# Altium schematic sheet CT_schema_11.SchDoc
size 385 x 278 mm
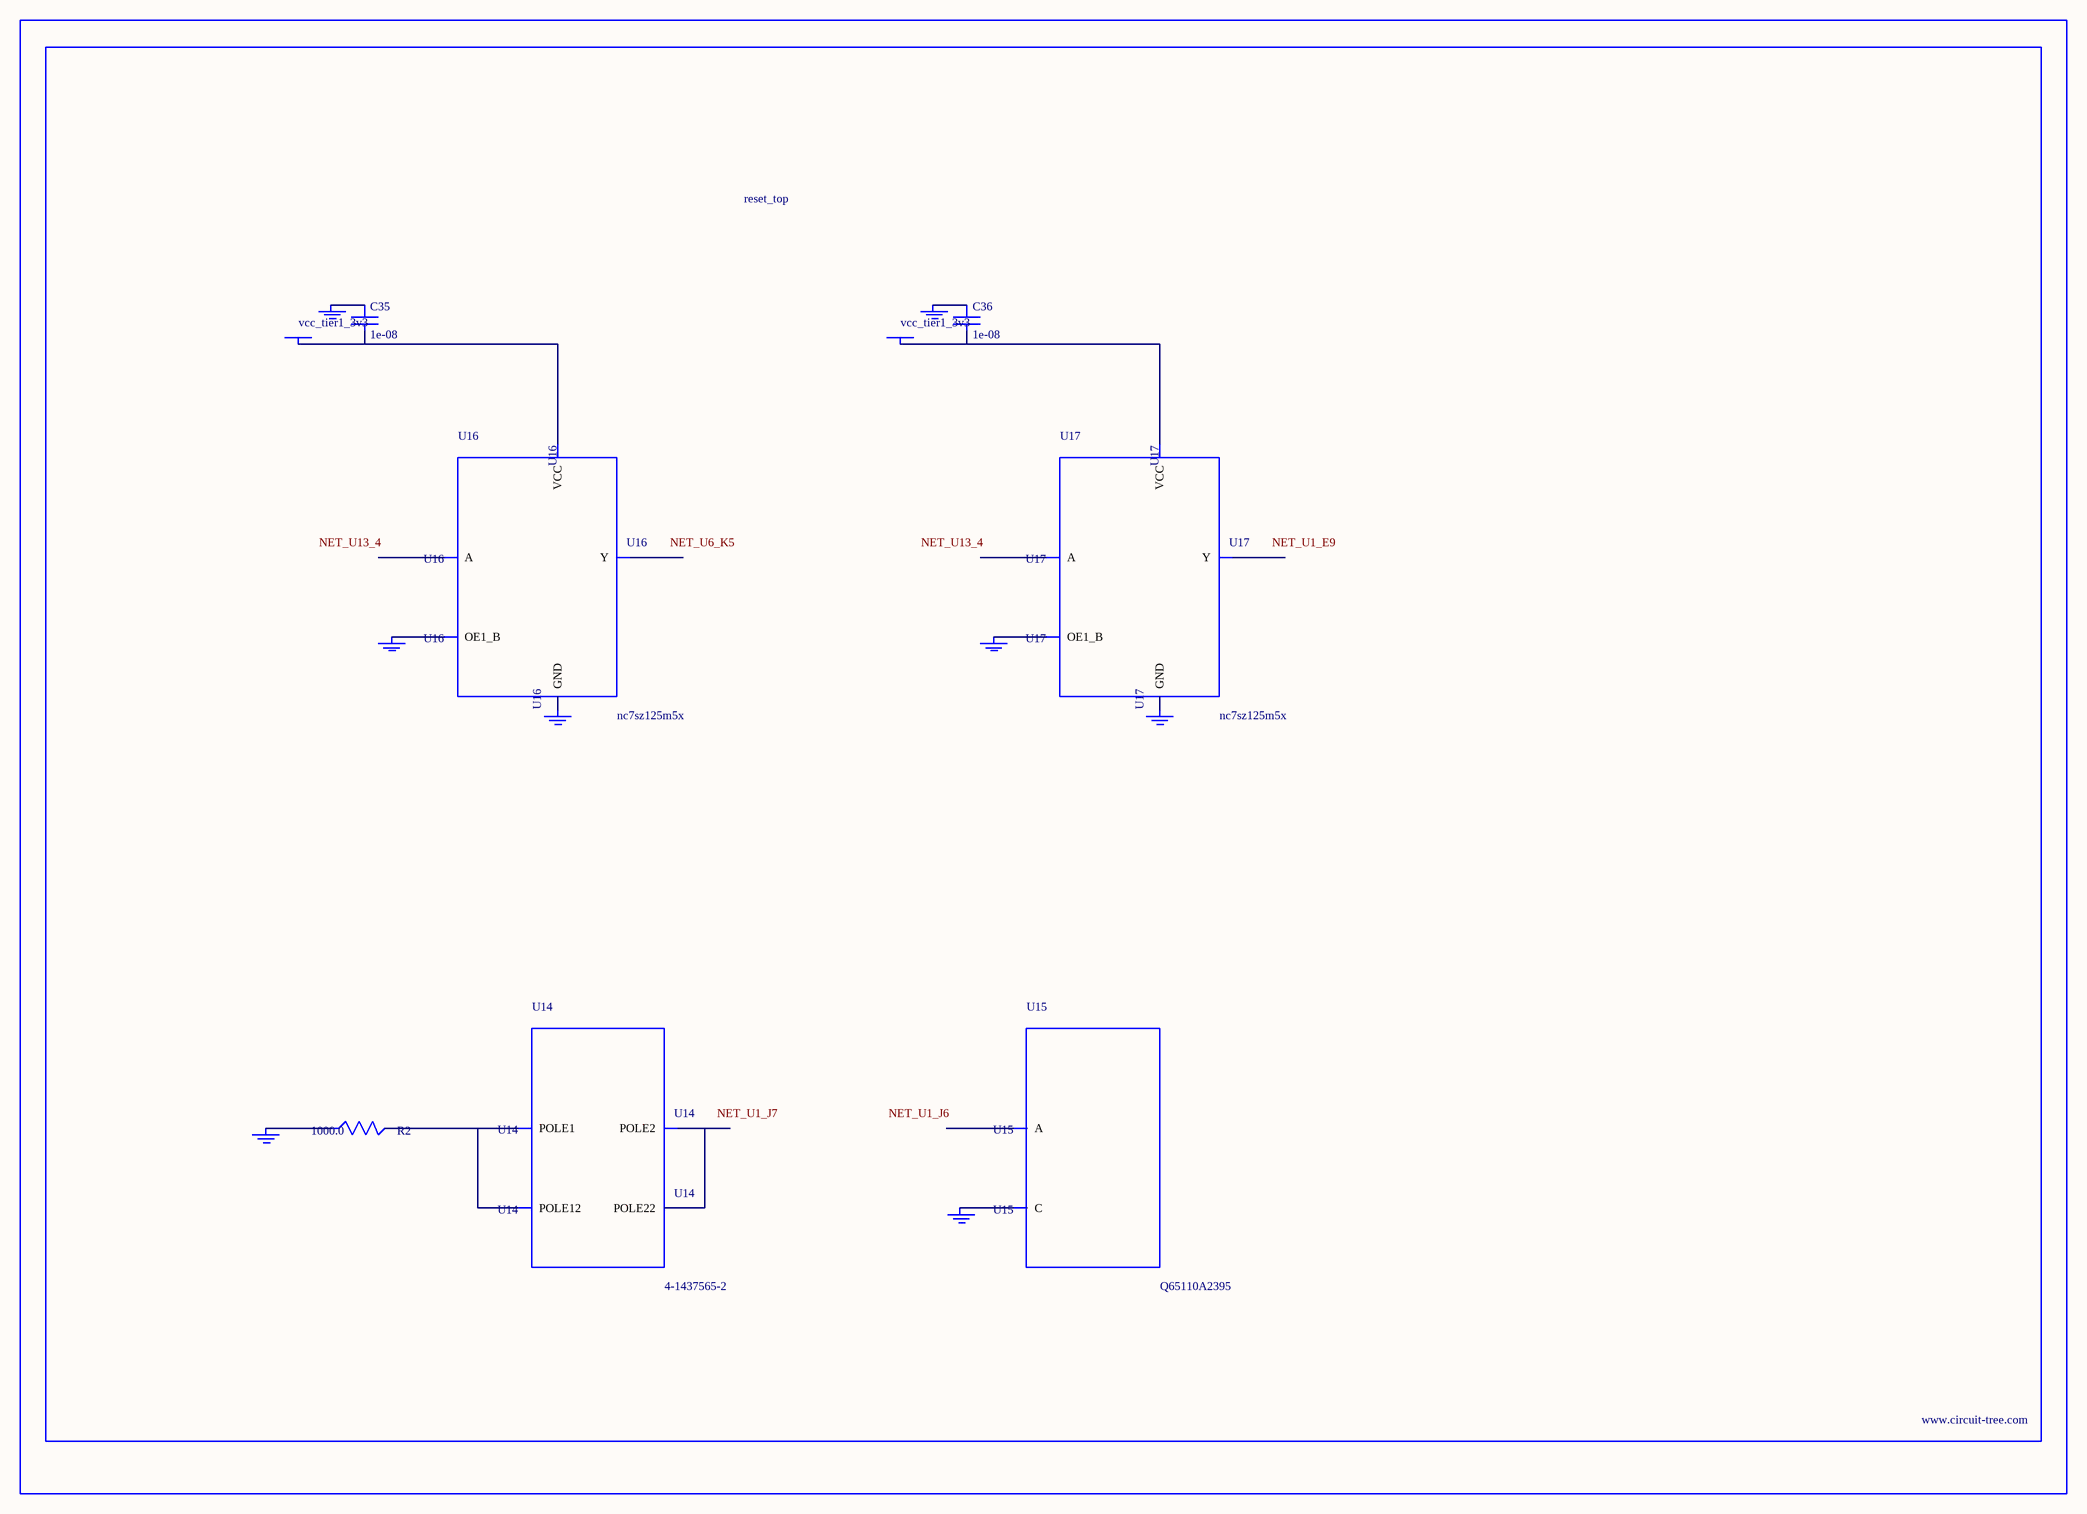
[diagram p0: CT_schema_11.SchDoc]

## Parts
BORDER10  (no value)
C35  1e-08  [C0402]
C36  1e-08  [C0402]
GND_INSTANCE_10_0  (no value)
GND_INSTANCE_10_1  (no value)
GND_INSTANCE_10_2  (no value)
GND_INSTANCE_10_3  (no value)
GND_INSTANCE_10_4  (no value)
GND_INSTANCE_10_5  (no value)
GND_INSTANCE_10_6  (no value)
GND_INSTANCE_10_7  (no value)
POWER_INSTANCE_10_0  vcc_tier1_3v3
POWER_INSTANCE_10_1  vcc_tier1_3v3
R2  1000.0  [R0603]
U14  4-1437565-2  [SW_4-1437565-2]
U15  Q65110A2395  [LGM67K-G1J2-24-Z]
U16  nc7sz125m5x  [NC7SZ125M5X]
U17  nc7sz125m5x  [NC7SZ125M5X]

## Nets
NetC35_1: C35.1 GND_INSTANCE_10_2.0(GND)
NetC35_2: C35.2 POWER_INSTANCE_10_0.0(PWR) U16.5(VCC)
NetC36_1: C36.1 GND_INSTANCE_10_5.0(GND)
NetC36_2: C36.2 POWER_INSTANCE_10_1.0(PWR) U17.5(VCC)
NetGND_INSTANCE_10_0_0: GND_INSTANCE_10_0.0(GND) R2.1
NetGND_INSTANCE_10_1_0: GND_INSTANCE_10_1.0(GND) U15.C
NetGND_INSTANCE_10_3_0: GND_INSTANCE_10_3.0(GND) U16.1(OE1_B)
NetGND_INSTANCE_10_4_0: GND_INSTANCE_10_4.0(GND) U16.3(GND)
NetGND_INSTANCE_10_6_0: GND_INSTANCE_10_6.0(GND) U17.1(OE1_B)
NetGND_INSTANCE_10_7_0: GND_INSTANCE_10_7.0(GND) U17.3(GND)
NetR2_2: R2.2 U14.1(POLE1) U14.2(POLE12)
NetU14_3: U14.3(POLE2) U14.4(POLE22)

Not connected (* = marked no-connect by the designer): U15 A; U16 2(A) 4(Y); U17 2(A) 4(Y)

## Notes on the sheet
- Labels drawn without touching a wire or pin: NET_U1_E9, NET_U1_J6, NET_U1_J7, NET_U6_K5, NET_U13_4

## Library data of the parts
BORDER10 = BORDER_PAGE10
C35 C36 = C0402C103K3RAC
GND_INSTANCE_10_0-GND_INSTANCE_10_7 = GND
POWER_INSTANCE_10_0 POWER_INSTANCE_10_1 = PWR
R2 = RC0603JR-071KL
